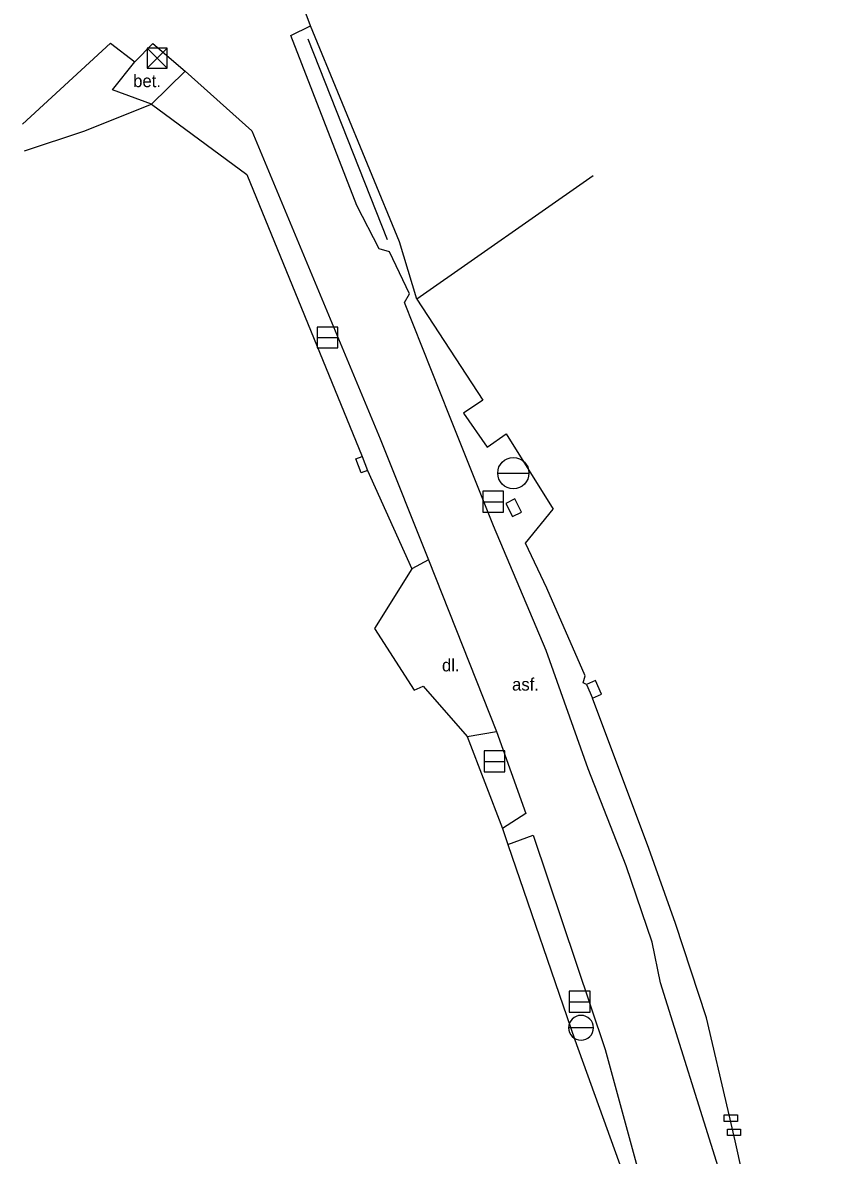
# Model space of a CAD drawing. Extents: x -719449 to -719090, y -950143 to -949819.
# Drawn here: x -719391.4 to -719342, y -950014.8 to -949946.8 of the extents above; entities that cross this region are included whole.
import ezdxf

# ---------------------------------------------------------------- set-up
doc = ezdxf.new("R2010")
doc.units = 0
for name, color, linetype in [('Budovy', 7, 'Continuous'), ('Doplňkové značky', 7, 'Continuous'), ('Ploty_opěrné zdi', 7, 'Continuous'), ('Popisy objektů_povrchů', 7, 'Continuous'), ('Rozhraní ploch', 7, 'Continuous'), ('Stromy_porost', 7, 'Continuous'), ('Vstup na pozemek', 7, 'Continuous'), ('Výškopis', 7, 'Continuous'), ('Značky IS', 7, 'Continuous')]:
    doc.layers.add(name, color=color, linetype=linetype)

msp = doc.modelspace()

# ---------------------------------------------------------------- linework, layer by layer
at = {"layer": 'Budovy'}
msp.add_lwpolyline([(-719357.11, -949955.95), (-719367.69, -949963.37), (-719363.74, -949969.43), (-719364.9, -949970.21), (-719363.47, -949972.26), (-719362.33, -949971.46), (-719359.51, -949975.98)], dxfattribs=at)
at = {"layer": 'Doplňkové značky'}
msp.add_line((-719362.838, -949973.82), (-719360.963, -949973.82), dxfattribs=at)
msp.add_circle((-719361.9, -949973.82), 0.938, dxfattribs=at)
at = {"layer": 'Ploty_opěrné zdi'}
for points in [[(-719368.73, -949959.92), (-719374.09, -949946.94)], [(-719383.64, -949951.64), (-719377.92, -949955.88), (-719370.98, -949972.82)], [(-719370.67, -949973.67), (-719367.99, -949979.58), (-719370.23, -949983.16)], [(-719357.51, -949986.53), (-719357.71, -949986.42), (-719357.59, -949986.01), (-719359.89, -949980.74), (-719361.17, -949978.04), (-719359.51, -949975.98)], [(-719367.85, -949986.86), (-719367.31, -949986.62)], [(-719353.75, -949996.39), (-719357.14, -949987.35)], [(-719364.67, -949989.66), (-719362.55, -949995.18)], [(-719362.23, -949996.15), (-719358.2, -950007.88), (-719354.35, -950018.55), (-719351.98, -950029.37), (-719352.57, -950031.49)], [(-719350.3, -950006.57), (-719352.15, -950000.89)], [(-719348.57, -950013.95), (-719349, -950012.13)], [(-719341.95, -950045.83), (-719344.66, -950031.63), (-719348.57, -950013.95)]]:
    msp.add_lwpolyline(points, dxfattribs=at)
at = {"layer": 'Rozhraní ploch'}
for points in [[(-719349.59, -950015.52), (-719353.05, -950004.45), (-719353.55, -950002.01), (-719355.12, -949997.42), (-719357.4, -949991.59), (-719359.92, -949984.49), (-719363.1, -949977), (-719365.74, -949970.39), (-719368.44, -949963.57), (-719368.14, -949963.05), (-719369.33, -949960.53), (-719369.96, -949960.35), (-719371.3, -949957.74), (-719375.27, -949947.53), (-719374.09, -949946.94)], [(-719391.38, -949952.86), (-719386.11, -949947.99), (-719384.64, -949949.11)], [(-719384.64, -949949.11), (-719383.55, -949948), (-719381.61, -949949.67)], [(-719381.61, -949949.67), (-719383.64, -949951.64), (-719385.99, -949950.78), (-719384.64, -949949.11)], [(-719381.61, -949949.67), (-719377.62, -949953.25), (-719369.9, -949971.76), (-719367, -949979.04), (-719367.99, -949979.58)], [(-719367, -949979.04), (-719362.91, -949989.36)], [(-719364.67, -949989.66), (-719362.91, -949989.36), (-719361.14, -949994.28), (-719362.55, -949995.18)], [(-719362.23, -949996.15), (-719360.71, -949995.59), (-719356.38, -950008.47), (-719350.78, -950029.03), (-719351.98, -950029.37)]]:
    msp.add_lwpolyline(points, dxfattribs=at)
at = {"layer": 'Stromy_porost'}
msp.add_lwpolyline([(-719387.7, -949953.28), (-719383.64, -949951.64)], dxfattribs=at)
at = {"layer": 'Vstup na pozemek'}
for points in [[(-719374.09, -949946.94), (-719374.46, -949945.91)], [(-719391.27, -949954.46), (-719387.7, -949953.28)], [(-719367.69, -949963.37), (-719368.73, -949959.92)], [(-719370.23, -949983.16), (-719367.85, -949986.86)], [(-719367.31, -949986.62), (-719364.67, -949989.66)], [(-719362.55, -949995.18), (-719362.23, -949996.15)], [(-719352.15, -950000.89), (-719353.75, -949996.39)], [(-719349, -950012.13), (-719350.3, -950006.57)]]:
    msp.add_lwpolyline(points, dxfattribs=at)
at = {"layer": 'Výškopis'}
msp.add_lwpolyline([(-719374.24, -949947.72), (-719369.48, -949959.79)], dxfattribs=at)
at = {"layer": 'Značky IS'}
for p, q in [((-719383.89, -949948.29), (-719382.69, -949949.49)), ((-719382.69, -949948.29), (-719383.89, -949949.49)), ((-719382.69, -949948.29), (-719383.89, -949948.29)), ((-719383.89, -949948.29), (-719383.89, -949949.49)), ((-719382.69, -949949.49), (-719382.69, -949948.29)), ((-719383.89, -949949.49), (-719382.69, -949949.49)), ((-719372.434, -949965.043), (-719373.686, -949965.043)), ((-719373.686, -949965.043), (-719373.686, -949966.297)), ((-719372.434, -949966.297), (-719372.434, -949965.043)), ((-719373.686, -949965.67), (-719372.436, -949965.67)), ((-719373.686, -949966.297), (-719372.434, -949966.297)), ((-719362.484, -949974.913), (-719363.736, -949974.913)), ((-719363.736, -949974.913), (-719363.736, -949976.167)), ((-719362.484, -949976.167), (-719362.484, -949974.913)), ((-719363.736, -949975.54), (-719362.486, -949975.54)), ((-719363.736, -949976.167), (-719362.484, -949976.167)), ((-719362.404, -949990.523), (-719363.655, -949990.523)), ((-719363.655, -949990.523), (-719363.655, -949991.777)), ((-719362.404, -949991.777), (-719362.404, -949990.523)), ((-719363.655, -949991.15), (-719362.405, -949991.15)), ((-719363.655, -949991.777), (-719362.404, -949991.777)), ((-719357.284, -950004.963), (-719358.535, -950004.963)), ((-719358.535, -950004.963), (-719358.535, -950006.217)), ((-719357.284, -950006.217), (-719357.284, -950004.963)), ((-719358.535, -950005.59), (-719357.285, -950005.59)), ((-719358.535, -950006.217), (-719357.284, -950006.217)), ((-719357.083, -950007.16), (-719358.578, -950007.16)), ((-719349.224, -950012.393), (-719348.436, -950012.393)), ((-719349.224, -950012.787), (-719349.224, -950012.393)), ((-719348.436, -950012.393), (-719348.436, -950012.787)), ((-719348.436, -950012.787), (-719349.224, -950012.787)), ((-719349.034, -950013.243), (-719348.246, -950013.243)), ((-719349.034, -950013.637), (-719349.034, -950013.243)), ((-719348.246, -950013.637), (-719349.034, -950013.637)), ((-719348.246, -950013.243), (-719348.246, -950013.637))]:
    msp.add_line(p, q, dxfattribs=at)
for points in [[(-719370.98, -949972.82), (-719370.67, -949973.67), (-719371.045, -949973.808), (-719371.045, -949973.808), (-719371.36, -949972.96), (-719370.98, -949972.82)], [(-719362.34, -949975.64), (-719361.94, -949976.43), (-719361.403, -949976.162), (-719361.403, -949976.162), (-719361.8, -949975.37)], [(-719361.8, -949975.37), (-719362.34, -949975.64)], [(-719357.51, -949986.53), (-719357.14, -949987.35), (-719356.594, -949987.102), (-719356.594, -949987.102), (-719356.97, -949986.28), (-719357.51, -949986.53)]]:
    msp.add_lwpolyline(points, dxfattribs=at)
for start, end in [(0, 180), (180, 0)]:
    msp.add_arc((-719357.83, -950007.16), 0.747, start, end, dxfattribs=at)

# ---------------------------------------------------------------- texts
at = {"layer": 'Popisy objektů_povrchů'}
for s, p in [('bet.', (-719384.741, -949950.627)), ('dl.', (-719366.186, -949985.74)), ('asf.', (-719361.976, -949986.893))]:
    msp.add_text(s, height=0.75, dxfattribs=at).set_placement(p)

doc.saveas('drawing.dxf')
